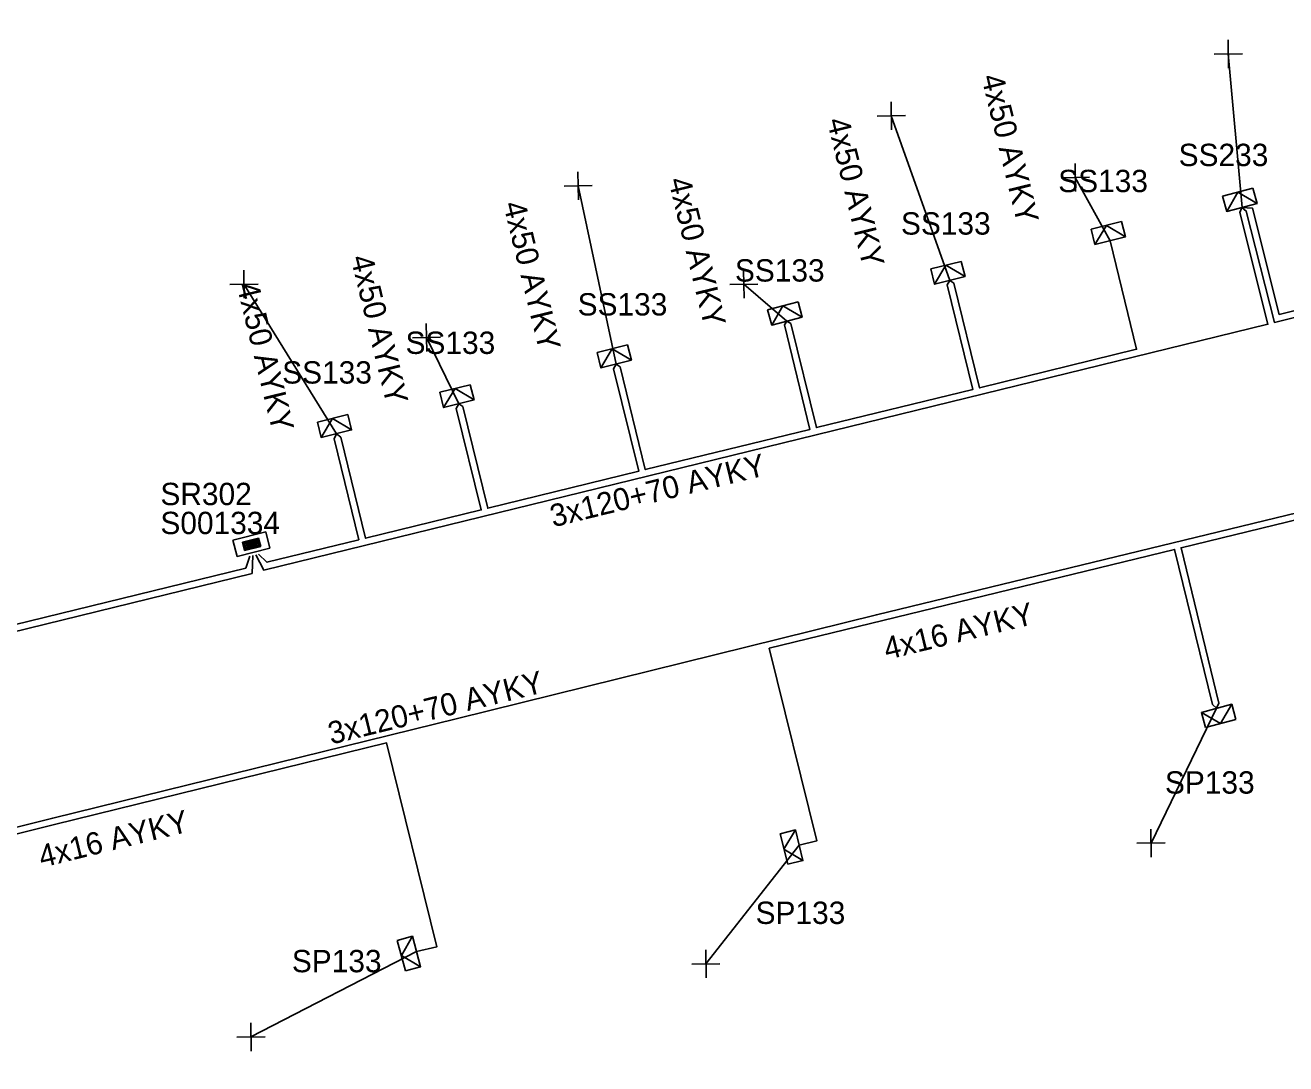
# Model space of a CAD drawing. Extents: x -762500 to -761285, y -1155006 to -1154135.
# Drawn here: x -762207.7 to -762151.6, y -1154604.1 to -1154557.9 of the extents above; entities that cross this region are included whole.
import ezdxf

# ---------------------------------------------------------------- set-up
doc = ezdxf.new("R2010")
doc.units = 0
for name, color, linetype in [('Vrstva 28', 7, 'Continuous'), ('Vrstva 29', 7, 'Continuous'), ('Vrstva 30', 7, 'Continuous'), ('Vrstva 31', 7, 'Continuous'), ('Vrstva 33', 7, 'Continuous'), ('Vrstva 34', 7, 'Continuous'), ('Vrstva 5', 7, 'Continuous'), ('Vrstva 59', 7, 'Continuous'), ('Vrstva 6', 7, 'Continuous')]:
    doc.layers.add(name, color=color, linetype=linetype)

msp = doc.modelspace()

# ---------------------------------------------------------------- linework, layer by layer
at = {"layer": 'Vrstva 28'}
for points in [[(-762197.035, -1154580.404), (-762198.49, -1154580.767)], [(-762198.49, -1154580.767), (-762198.309, -1154581.495)], [(-762197.35, -1154580.678), (-762198.072, -1154580.858)], [(-762197.384, -1154580.735), (-762198.015, -1154580.892)], [(-762197.419, -1154580.792), (-762197.957, -1154580.927)], [(-762197.373, -1154580.976), (-762197.419, -1154580.792)], [(-762197.316, -1154581.01), (-762197.384, -1154580.735)], [(-762197.258, -1154581.045), (-762197.35, -1154580.678)], [(-762196.853, -1154581.132), (-762197.035, -1154580.404)], [(-762198.309, -1154581.495), (-762196.853, -1154581.132)], [(-762198.072, -1154580.858), (-762197.98, -1154581.225)], [(-762198.015, -1154580.892), (-762197.946, -1154581.167)], [(-762197.98, -1154581.225), (-762197.258, -1154581.045)], [(-762197.957, -1154580.927), (-762197.912, -1154581.11)], [(-762197.946, -1154581.167), (-762197.316, -1154581.01)], [(-762197.912, -1154581.11), (-762197.373, -1154580.976)], [(-762197.453, -1154580.85), (-762197.9, -1154580.961)], [(-762197.9, -1154580.961), (-762197.877, -1154581.053)], [(-762197.877, -1154581.053), (-762197.43, -1154580.941)], [(-762197.482, -1154580.905), (-762197.848, -1154580.997)], [(-762197.43, -1154580.941), (-762197.453, -1154580.85)]]:
    msp.add_lwpolyline(points, dxfattribs=at)
at = {"layer": 'Vrstva 31'}
for points in [[(-762153.092, -1154565.102), (-762154.444, -1154565.464)], [(-762153.092, -1154565.102), (-762152.911, -1154565.778), (-762154.263, -1154566.14), (-762154.444, -1154565.464)], [(-762153.768, -1154565.283), (-762154.263, -1154566.14)], [(-762153.768, -1154565.283), (-762152.911, -1154565.778)], [(-762158.937, -1154566.59), (-762160.295, -1154566.929)], [(-762158.937, -1154566.59), (-762158.768, -1154567.27), (-762160.126, -1154567.608), (-762160.295, -1154566.929)], [(-762159.616, -1154566.76), (-762160.126, -1154567.608)], [(-762159.616, -1154566.76), (-762158.768, -1154567.27)], [(-762166.077, -1154568.36), (-762167.435, -1154568.699)], [(-762166.077, -1154568.36), (-762165.908, -1154569.039), (-762167.266, -1154569.378), (-762167.435, -1154568.699)], [(-762166.756, -1154568.529), (-762167.266, -1154569.378)], [(-762166.756, -1154568.529), (-762165.908, -1154569.039)], [(-762173.342, -1154570.161), (-762174.694, -1154570.524)], [(-762173.342, -1154570.161), (-762173.161, -1154570.838), (-762174.513, -1154571.2), (-762174.694, -1154570.524)], [(-762174.018, -1154570.343), (-762174.513, -1154571.2)], [(-762174.018, -1154570.343), (-762173.161, -1154570.838)], [(-762180.928, -1154572.081), (-762182.286, -1154572.419)], [(-762180.928, -1154572.081), (-762180.759, -1154572.76), (-762182.117, -1154573.099), (-762182.286, -1154572.419)], [(-762181.607, -1154572.25), (-762182.117, -1154573.099)], [(-762181.607, -1154572.25), (-762180.759, -1154572.76)], [(-762187.927, -1154573.85), (-762189.285, -1154574.189)], [(-762187.927, -1154573.85), (-762187.758, -1154574.529), (-762189.116, -1154574.868), (-762189.285, -1154574.189)], [(-762188.606, -1154574.019), (-762189.116, -1154574.868)], [(-762188.606, -1154574.019), (-762187.758, -1154574.529)], [(-762193.377, -1154575.18), (-762194.735, -1154575.519)], [(-762193.377, -1154575.18), (-762193.208, -1154575.859), (-762194.566, -1154576.198), (-762194.735, -1154575.519)], [(-762194.056, -1154575.349), (-762194.566, -1154576.198)], [(-762194.056, -1154575.349), (-762193.208, -1154575.859)], [(-762155.208, -1154589.109), (-762155.389, -1154588.433), (-762154.037, -1154588.07), (-762153.855, -1154588.746)], [(-762154.532, -1154588.928), (-762154.037, -1154588.07)], [(-762154.532, -1154588.928), (-762155.389, -1154588.433)], [(-762155.208, -1154589.109), (-762153.855, -1154588.746)], [(-762174.139, -1154593.837), (-762173.46, -1154593.668), (-762173.121, -1154595.026), (-762173.801, -1154595.196)], [(-762173.97, -1154594.516), (-762173.46, -1154593.668)], [(-762174.139, -1154593.837), (-762173.801, -1154595.196)], [(-762173.97, -1154594.516), (-762173.121, -1154595.026)], [(-762191.178, -1154598.582), (-762190.502, -1154598.401), (-762190.14, -1154599.753), (-762190.816, -1154599.934)], [(-762191.178, -1154598.582), (-762190.816, -1154599.934)], [(-762190.997, -1154599.258), (-762190.502, -1154598.401)], [(-762190.997, -1154599.258), (-762190.14, -1154599.753)]]:
    msp.add_lwpolyline(points, dxfattribs=at)
at = {"layer": 'Vrstva 34'}
for points in [[(-762154.179, -1154559.755), (-762154.201, -1154558.505)], [(-762154.815, -1154559.141), (-762153.565, -1154559.119)], [(-762169.179, -1154562.505), (-762169.201, -1154561.255)], [(-762169.815, -1154561.891), (-762168.565, -1154561.869)], [(-762183.119, -1154565.625), (-762183.141, -1154564.375)], [(-762160.989, -1154565.255), (-762161.011, -1154564.005)], [(-762183.755, -1154565.011), (-762182.505, -1154564.989)], [(-762161.625, -1154564.641), (-762160.375, -1154564.619)], [(-762197.989, -1154570.005), (-762198.011, -1154568.755)], [(-762175.739, -1154570.005), (-762175.761, -1154568.755)], [(-762198.625, -1154569.391), (-762197.375, -1154569.369)], [(-762176.375, -1154569.391), (-762175.125, -1154569.369)], [(-762189.869, -1154572.375), (-762189.891, -1154571.125)], [(-762190.505, -1154571.761), (-762189.255, -1154571.739)], [(-762157.619, -1154594.875), (-762157.641, -1154593.625)], [(-762158.255, -1154594.261), (-762157.005, -1154594.239)], [(-762177.429, -1154600.255), (-762177.451, -1154599.005)], [(-762178.065, -1154599.641), (-762176.815, -1154599.619)], [(-762197.679, -1154603.505), (-762197.701, -1154602.255)], [(-762198.315, -1154602.891), (-762197.065, -1154602.869)]]:
    msp.add_lwpolyline(points, dxfattribs=at)
at = {"layer": 'Vrstva 5'}
for points in [[(-762121.03, -1154557.85), (-762121.12, -1154558.12), (-762119.89, -1154563.07), (-762152.14, -1154571.08), (-762153.39, -1154566.12), (-762153.59, -1154565.96)], [(-762153.59, -1154565.96), (-762153.12, -1154565.99), (-762151.93, -1154570.72), (-762143.9, -1154568.72), (-762145.04, -1154564.01), (-762144.94, -1154563.78), (-762144.75, -1154563.96), (-762143.6, -1154568.65), (-762135.97, -1154566.75), (-762137.19, -1154561.85)], [(-762153.59, -1154565.96), (-762153.68, -1154566.19), (-762152.43, -1154571.16), (-762197.12, -1154582.1), (-762197.48, -1154581.42)], [(-762197.36, -1154581.39), (-762196.98, -1154581.75), (-762192.89, -1154580.75), (-762193.98, -1154576.26), (-762193.89, -1154576.03), (-762193.69, -1154576.19), (-762192.59, -1154580.68), (-762187.44, -1154579.42), (-762188.55, -1154574.91), (-762188.44, -1154574.7), (-762188.26, -1154574.82), (-762187.15, -1154579.35), (-762180.43, -1154577.7), (-762181.55, -1154573.14), (-762181.44, -1154572.93), (-762181.26, -1154573.06), (-762180.14, -1154577.63), (-762172.81, -1154575.84), (-762173.95, -1154571.19), (-762173.84, -1154571.02), (-762173.66, -1154571.13), (-762172.52, -1154575.76), (-762165.56, -1154574.06), (-762166.7, -1154569.41), (-762166.59, -1154569.21), (-762166.41, -1154569.33), (-762165.26, -1154573.99), (-762158.27, -1154572.27), (-762159.45, -1154567.44)], [(-762144.24, -1154589.69), (-762144.5, -1154589.93), (-762146.6, -1154590.48), (-762149.55, -1154579.17), (-762169.85, -1154584.09), (-762188.5, -1154588.71), (-762206.51, -1154593.14), (-762225.77, -1154597.95), (-762230.65, -1154599.12), (-762227.01, -1154614.44), (-762229.36, -1154614.99), (-762229.4, -1154614.91)], [(-762144.24, -1154589.69), (-762144.42, -1154590.22), (-762146.81, -1154590.84), (-762149.77, -1154579.53), (-762156.29, -1154581.11), (-762154.61, -1154588.02), (-762154.71, -1154588.25), (-762154.9, -1154588.08), (-762156.58, -1154581.18), (-762174.62, -1154585.58), (-762172.5, -1154594.15), (-762173.29, -1154594.35)], [(-762197.61, -1154581.45), (-762197.64, -1154582.25), (-762252.17, -1154595.62), (-762253.42, -1154590.57)], [(-762197.74, -1154581.48), (-762197.92, -1154582.01), (-762224.8, -1154588.59), (-762226.02, -1154583.64)], [(-762229.37, -1154615.04), (-762229.27, -1154615.28), (-762226.64, -1154614.66), (-762230.29, -1154599.34), (-762215.35, -1154595.65), (-762213.56, -1154602.8), (-762213.37, -1154602.96), (-762213.27, -1154602.72), (-762215.06, -1154595.58), (-762206.44, -1154593.43), (-762191.65, -1154589.79), (-762189.42, -1154598.87), (-762190.32, -1154599.08)]]:
    msp.add_lwpolyline(points, dxfattribs=at)
at = {"layer": 'Vrstva 59'}
for points in [[(-762153.58, -1154565.96), (-762154.19, -1154559.13)], [(-762166.59, -1154569.21), (-762169.19, -1154561.88)], [(-762181.44, -1154572.93), (-762183.13, -1154565)], [(-762159.45, -1154567.44), (-762161, -1154564.63)], [(-762193.89, -1154576.03), (-762198, -1154569.38)], [(-762173.84, -1154571.02), (-762175.75, -1154569.38)], [(-762188.44, -1154574.7), (-762189.88, -1154571.75)], [(-762154.71, -1154588.25), (-762157.63, -1154594.25)], [(-762173.29, -1154594.35), (-762177.44, -1154599.63)], [(-762190.32, -1154599.08), (-762197.69, -1154602.88)]]:
    msp.add_lwpolyline(points, dxfattribs=at)

# ---------------------------------------------------------------- texts
at = {"layer": 'Vrstva 29'}
msp.add_text('S001334', height=0.9943, dxfattribs=at).set_placement((-762201.72, -1154580.5))
at = {"layer": 'Vrstva 30'}
msp.add_text('SR302', height=0.9943, dxfattribs=at).set_placement((-762201.72, -1154579.21))
at = {"layer": 'Vrstva 33'}
for s, p in [('SS233', (-762156.4, -1154564.12)), ('SS133', (-762161.76, -1154565.28)), ('SS133', (-762168.76, -1154567.17)), ('SS133', (-762176.15, -1154569.26)), ('SS133', (-762183.15, -1154570.77)), ('SS133', (-762190.81, -1154572.48)), ('SS133', (-762196.3, -1154573.8)), ('SP133', (-762157.01, -1154592.05)), ('SP133', (-762175.23, -1154597.85)), ('SP133', (-762195.87, -1154600))]:
    msp.add_text(s, height=0.9943, dxfattribs=at).set_placement(p)
at = {"layer": 'Vrstva 6'}
for s, height, rotation, p in [('4x50 AYKY', 0.9943, 283.7546, (-762165.19, -1154560.15)), ('4x50 AYKY', 0.9943, 283.7533, (-762172.06, -1154562.09)), ('4x50 AYKY', 0.9943, 283.7579, (-762179.12, -1154564.74)), ('4x50 AYKY', 0.9943, 283.7591, (-762186.47, -1154565.81)), ('4x50 AYKY', 0.9943, 283.7584, (-762193.26, -1154568.2)), ('4x50 AYKY', 0.9943, 283.7524, (-762198.34, -1154569.41)), ('3x120+70 AYKY', 0.99429, 13.7596, (-762184.24, -1154580.2)), ('4x16 AYKY', 0.9943, 13.71, (-762169.39, -1154586.1)), ('3x120+70 AYKY', 0.99428, 13.8047, (-762194.12, -1154589.87)), ('4x16 AYKY', 0.9943, 13.8063, (-762207, -1154595.35))]:
    msp.add_text(s, height=height, rotation=rotation, dxfattribs=at).set_placement(p)

doc.saveas('drawing.dxf')
